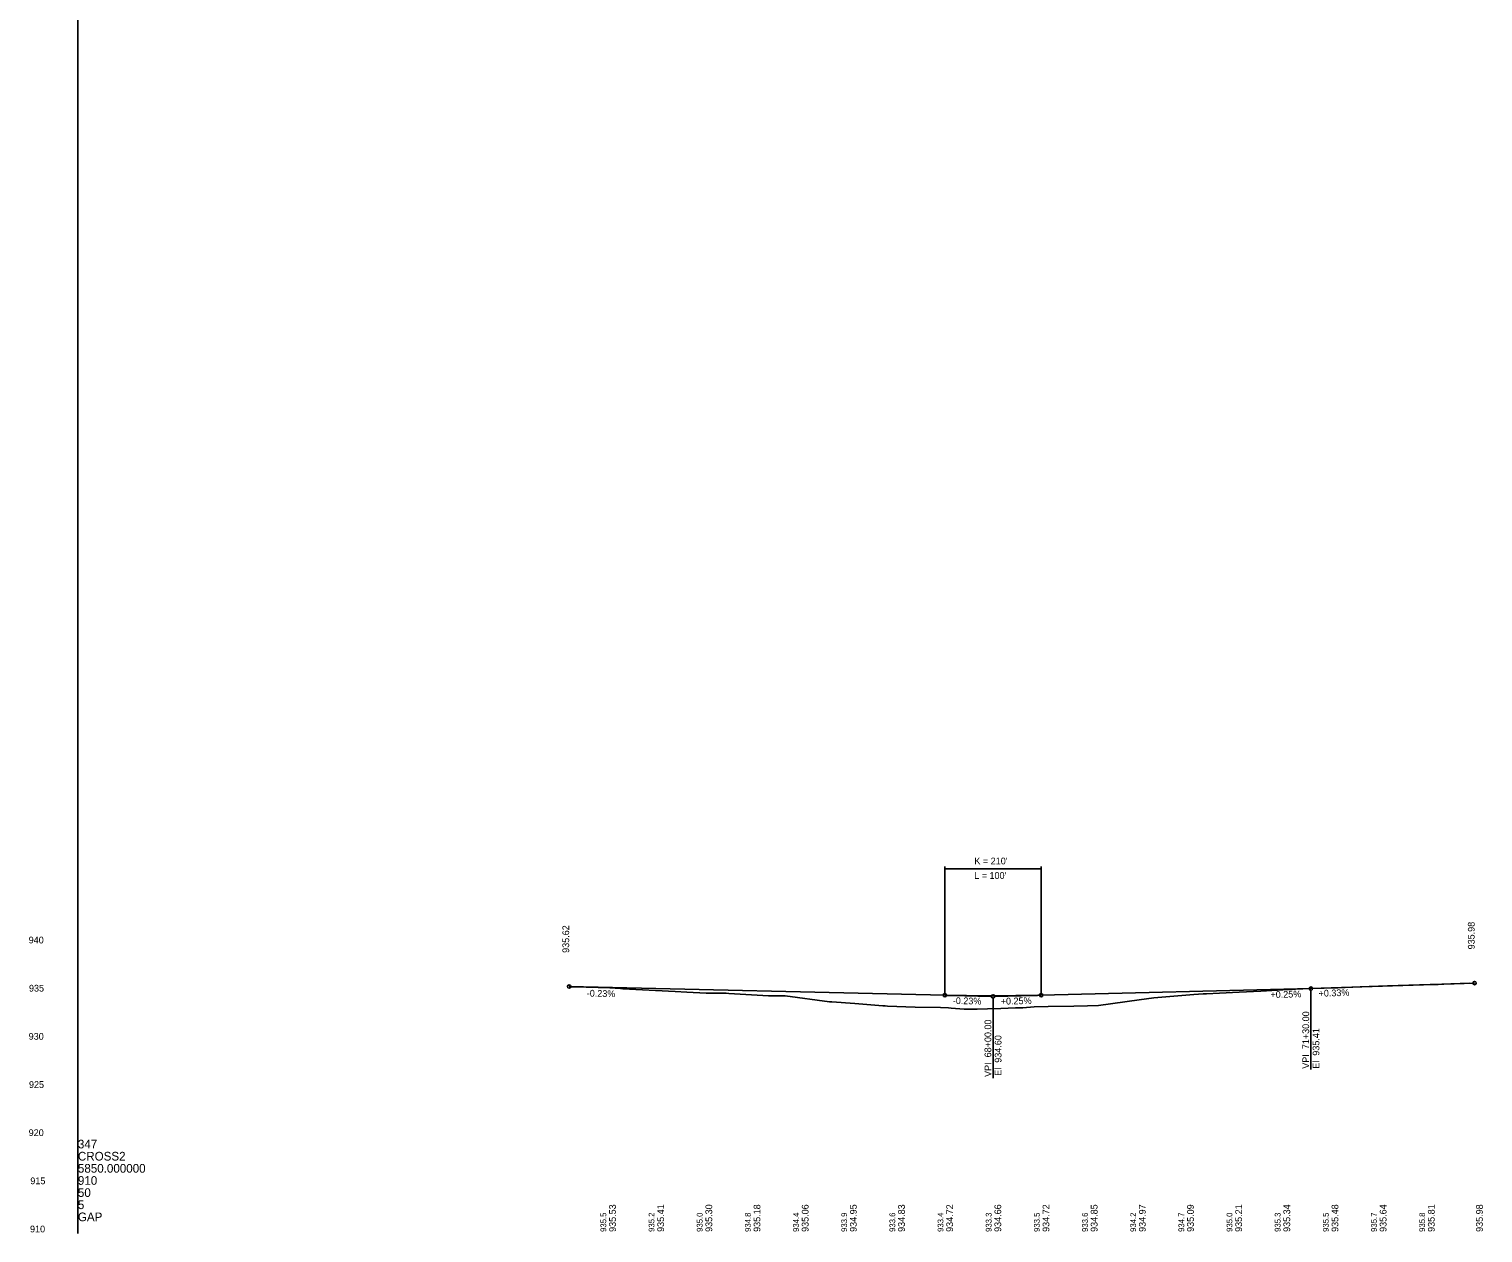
# Model space of a CAD drawing. Extents: x 356949 to 358500, y 195500 to 200500.
# Drawn here: x 356949 to 358459, y 198000 to 199250 of the extents above; entities that cross this region are included whole.
import ezdxf

# ---------------------------------------------------------------- set-up
doc = ezdxf.new("R2010")
doc.units = 0
for name, color, linetype in [('Default', 7, 'Continuous'), ('E_PROF_Grades', 7, 'Continuous'), ('P_E_PROF', 7, 'Continuous'), ('P_PROF', 7, 'Continuous'), ('P_PROF_Grades', 7, 'Continuous')]:
    doc.layers.add(name, color=color, linetype=linetype)

msp = doc.modelspace()

# ---------------------------------------------------------------- linework, layer by layer
at = {"layer": 'Default'}
msp.add_line((357000, 198000), (357000, 200500), dxfattribs=at)
at = {"layer": 'P_E_PROF'}
msp.add_lwpolyline([(357511.1, 198256.2), (357512.1, 198256.1), (357515.4, 198256), (357552.3, 198255), (357563.3, 198254.1), (357565.8, 198253.9), (357620.1, 198251.1), (357632, 198250.5), (357652.3, 198249.5), (357673.1, 198249.2), (357675.9, 198248.9), (357716.9, 198246.7), (357734.2, 198246.5), (357780.4, 198240.5), (357782.7, 198240.2), (357806.7, 198238.5), (357835.6, 198236.3), (357837.2, 198236.2), (357838.2, 198236.1), (357840.6, 198236), (357869.2, 198234.9), (357895.4, 198234.6), (357903.8, 198234), (357906.6, 198233.7), (357920, 198232.8), (357929.1, 198232.7), (357933.6, 198232.7), (357944.2, 198233.1), (357958, 198233.3), (357973.4, 198234), (357980.8, 198234), (357992.9, 198235.1), (358007.4, 198235.4), (358033.9, 198235.8), (358048, 198236.1), (358059.5, 198236.6), (358101.8, 198242.5), (358116.8, 198244.4), (358154.3, 198247.7), (358158.5, 198247.8), (358168.2, 198248.5), (358171.8, 198248.8), (358185.3, 198249.5), (358205.4, 198250.5), (358228.2, 198251.5), (358256.9, 198253.1), (358263.9, 198253.4), (358279.6, 198254.1), (358307.9, 198254.9), (358331.1, 198255.8), (358359.5, 198257), (358403.8, 198258.2), (358412, 198258.5), (358416.1, 198258.6), (358444.4, 198259.6)], dxfattribs=at)
at = {"layer": 'P_PROF'}
for p, q in [((357510, 198256.2), (357900, 198247.2)), ((358000, 198247.2), (358280, 198254.1)), ((358280, 198254.1), (358450, 198259.8))]:
    msp.add_line(p, q, dxfattribs=at)
msp.add_spline([(357900, 198247.2), (357902, 198247.1), (357904, 198247.1), (357906, 198247), (357908, 198247), (357910, 198247), (357912, 198246.9), (357914, 198246.9), (357916, 198246.8), (357918, 198246.8), (357920, 198246.8), (357922, 198246.8), (357924, 198246.7), (357926, 198246.7), (357928, 198246.7), (357930, 198246.7), (357932, 198246.7), (357934, 198246.6), (357936, 198246.6), (357938, 198246.6), (357940, 198246.6), (357942, 198246.6), (357944, 198246.6), (357946, 198246.6), (357948, 198246.6), (357950, 198246.6), (357952, 198246.6), (357954, 198246.6), (357956, 198246.6), (357958, 198246.6), (357960, 198246.6), (357962, 198246.6), (357964, 198246.7), (357966, 198246.7), (357968, 198246.7), (357970, 198246.7), (357972, 198246.7), (357974, 198246.8), (357976, 198246.8), (357978, 198246.8), (357980, 198246.8), (357982, 198246.9), (357984, 198246.9), (357986, 198246.9), (357988, 198247), (357990, 198247), (357992, 198247), (357994, 198247.1), (357996, 198247.1), (357998, 198247.2), (358000, 198247.2)], degree=3, dxfattribs=at)
at = {"layer": 'P_PROF_Grades'}
for p, q in [((357900, 198381), (357900, 198248.9)), ((358000, 198381), (358000, 198249)), ((357900, 198378.5), (358000, 198378.5)), ((357907, 198247), (357948.2, 198246)), ((357993, 198247.1), (357951.7, 198246)), ((358280, 198252.4), (358280, 198170.1)), ((357950, 198244.2), (357950, 198161.2))]:
    msp.add_line(p, q, dxfattribs=at)
for centre in [(358450, 198259.8), (357510, 198256.2), (357900, 198247.2), (357950, 198246), (358000, 198247.2), (358280, 198254.1)]:
    msp.add_circle(centre, 1.75, dxfattribs=at)

# ---------------------------------------------------------------- texts
at = {"layer": 'Default'}
for s, p in [('347', (357000, 198088.2)), ('CROSS2', (357000, 198075.6)), ('5850.000000', (357000, 198063)), ('910', (357000, 198050.4)), ('50', (357000, 198037.8)), ('5', (357000, 198025.2)), ('GAP', (357000, 198012.6))]:
    msp.add_text(s, height=9, dxfattribs=at).set_placement(p)
at = {"layer": 'E_PROF_Grades'}
for s, p in [('940', (356948.9, 198301)), ('935', (356949.2, 198251)), ('930', (356948.9, 198201)), ('925', (356949.2, 198151)), ('920', (356948.9, 198101)), ('915', (356950.6, 198051)), ('910', (356950.3, 198001))]:
    msp.add_text(s, height=7, dxfattribs=at).set_placement(p)
for s, p in [('935.5', (357548.5, 198001.5)), ('935.2', (357598.5, 198001.5)), ('935.0', (357648.5, 198001.5)), ('934.8', (357698.5, 198001.5)), ('934.4', (357748.5, 198001.5)), ('933.9', (357798.5, 198001.5)), ('933.6', (357848.5, 198001.5)), ('933.4', (357898.5, 198001.5)), ('933.3', (357948.5, 198001.5)), ('933.5', (357998.5, 198001.5)), ('933.6', (358048.5, 198001.5)), ('934.2', (358098.5, 198001.5)), ('934.7', (358148.5, 198001.5)), ('935.0', (358198.5, 198001.5)), ('935.3', (358248.5, 198001.5)), ('935.5', (358298.5, 198001.5)), ('935.7', (358348.5, 198001.5)), ('935.8', (358398.5, 198001.5))]:
    msp.add_text(s, height=6, rotation=90, dxfattribs=at).set_placement(p)
at = {"layer": 'P_PROF_Grades'}
for s, p in [("K = 210'", (357930.7, 198383.1)), ("L = 100'", (357930.5, 198368))]:
    msp.add_text(s, height=7, dxfattribs=at).set_placement(p)
for s, rotation, p in [('935.98', 90, (358450, 198294.8)), ('935.62', 90, (357510, 198291.2)), ('-0.23%', 358.6727, (357528.2, 198245.9)), ('-0.23%', 358.6727, (357908.2, 198238.2)), ('+0.25%', 1.4061, (357958.1, 198237.4)), ('+0.25%', 1.4061, (358238.1, 198244.3)), ('+0.33%', 1.9092, (358288.1, 198245.6)), ('VPI  71+30.00', 90, (358278.2, 198170.9)), ('VPI  68+00.00', 90, (357948.2, 198162.4)), ('El  934.60', 90, (357958.8, 198163.6)), ('El  935.41', 90, (358288.8, 198170.9)), ('935.53', 90, (357558.5, 198001.5)), ('935.41', 90, (357608.5, 198001.5)), ('935.30', 90, (357658.5, 198001.5)), ('935.18', 90, (357708.5, 198001.5)), ('935.06', 90, (357758.5, 198001.5)), ('934.95', 90, (357808.5, 198001.5)), ('934.83', 90, (357858.5, 198001.5)), ('934.72', 90, (357908.5, 198001.5)), ('934.66', 90, (357958.5, 198001.5)), ('934.72', 90, (358008.5, 198001.5)), ('934.85', 90, (358058.5, 198001.5)), ('934.97', 90, (358108.5, 198001.5)), ('935.09', 90, (358158.5, 198001.5)), ('935.21', 90, (358208.5, 198001.5)), ('935.34', 90, (358258.5, 198001.5)), ('935.48', 90, (358308.5, 198001.5)), ('935.64', 90, (358358.5, 198001.5)), ('935.81', 90, (358408.5, 198001.5)), ('935.98', 90, (358458.5, 198001.5))]:
    msp.add_text(s, height=7, rotation=rotation, dxfattribs=at).set_placement(p)

doc.saveas('drawing.dxf')
